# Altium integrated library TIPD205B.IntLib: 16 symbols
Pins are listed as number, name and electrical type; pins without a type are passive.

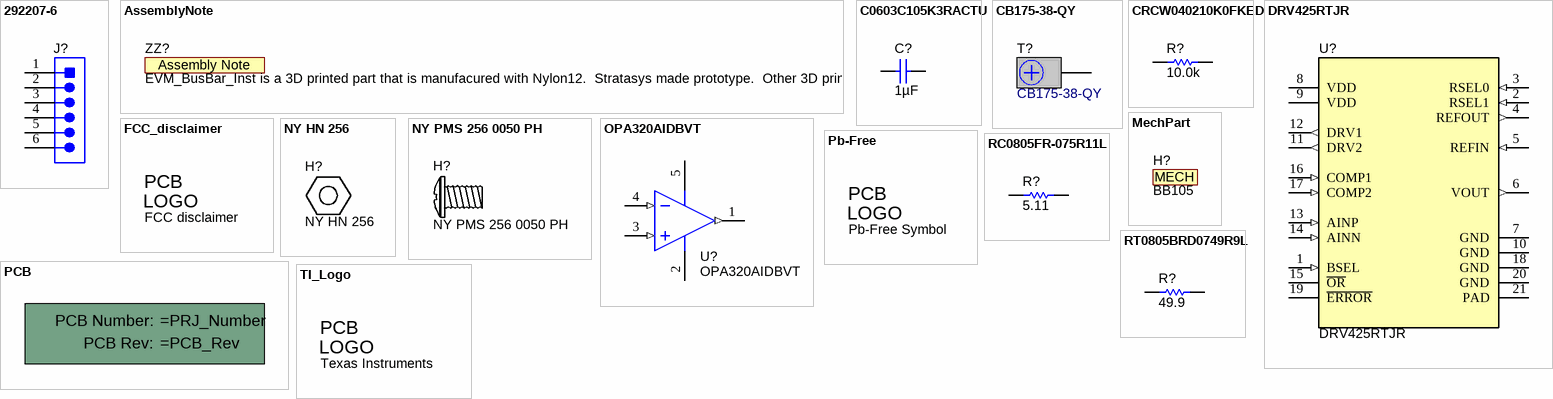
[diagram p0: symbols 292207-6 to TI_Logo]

## 292207-6
designator J?  (value not drawn)
Header(shrouded), 1.5mm, 6x1, Tin, TH; Manufacturer: TE Connectivity; SymbolCreator: a0412235; Pitch_mm: 1.5; Gender: Male; Shrouded: Y; Row_Count: 1; Current_A: 2; Voltage_V: 50
footprint TE_292207-6
pins: 1, 2, 3, 4, 5, 6

## AssemblyNote
designator ZZ?, comment EVM_BusBar_Inst is a 3D printed part that is manufacured with Nylon12.  Stratasys made prototype.  Other 3D print manufacure can be used.  File types provided (SLDPRT, STEP, STL)  (no BOM)
SymbolCreator: codlsc; CompType: AssemblyNote
footprint AssemblyNote

## C0603C105K3RACTU
designator C?  ValueDisplayed: 1µF  (hidden comment: C0603C105K3RACTU)
CAP, CERM, 1 µF, 25 V, +/- 10%, X7R, 0603; Manufacturer: Kemet; Polarized: N; CompType: Capacitor; Value: 1uF; U/M: EA; Cap_F: 0.000001; Tolerance_%: 10; Value1: Unknown; VDC_V: 25; Value2: 25V; TaMin_C: -55; TaMax_C: 125; Cap_Case: 0603; SizeArea_mm2: 1.28; SizeAreaWB_mm2: 4.68; SizeX_mm: 1.6; SizeY_mm: 0.8; SizeZ_mm: 1; AEC Category: Q200
signal-integrity model Cap
simulation model Cap
footprint 0603
footprint 0603M
footprint 0603L
footprint 0603_HV
footprint 0603S
pins: 1, 2

## CB175-38-QY
designator T?
Lug, Rectangular, 3/0-4 AWG, 3/8 Stud, with screw; Manufacturer: Panduit; SymbolCreator: crossc
footprint Panduit_CB175-38-QY
pins: 1

## CRCW040210K0FKED
designator R?  ValueDisplayed: 10.0k  (hidden comment: CRCW040210K0FKED)
RES, 10.0 k, 1%, 0.063 W, 0402; Manufacturer: Vishay-Dale; CompType: Resistor; Value: 10.0k; U/M: EA; Res_ohm: 10000; Value_Code: 10k0; Tolerance_%: 1; Power_W: 0.063; Value2: 0.063W; VDC_V: 50; TempCo: 100 ppm/C; SizeArea_mm2: 0.5; SizeZ_mm: 0.6; EIA_Code: E96; AEC Category: Q200
signal-integrity model Resistor
simulation model Resistor
footprint 0402
footprint 0402M
footprint 0402L
footprint 0402S
pins: 1, 2

## DRV425RTJR
designator U?
Fully Integrated Precision Fluxgate Magnetic Field Sensor and readout, RTJ0020G (WQFN-20); Alternate PartNumber: DRV425RTJT; Manufacturer: Texas Instruments; SymbolCreator: Altium; CompType: IC; U/M: EA; SizeArea_mm2: 16; SizeAreaWB_mm2: 25; SizeX_mm: 4; SizeZ_mm: 0.8
footprint RTJ0020G
footprint RTJ20_no_vias
pins: 1 BSEL (in), 2 RSEL1 (in), 3 RSEL0 (in), 4 REFOUT (out), 5 REFIN (in), 6 VOUT (out), 7 GND (power), 8 VDD (power), 9 VDD (power), 10 GND (power), 11 DRV2 (out), 12 DRV1 (out), 13 AINP (in), 14 AINN (in), 15 ~{OR} (oc), 16 COMP1 (in), 17 COMP2 (in), 18 GND (power), 19 ~{ERROR} (oc), 20 GND (power), 21 PAD (power)

## FCC_disclaimer
designator Logo?, comment FCC disclaimer  (no BOM)
FCC_disclaimer; SymbolCreator: a0412235
footprint FCC_disclaimer
footprint FCC_disclaimer_stacked

## MechPart
designator H?, comment BB105  (mechanical)
Bus bar 0.4" hole, standoffs, nuts, washers; Manufacturer: Storm Power Components; SymbolCreator: codlsc; CompType: Mechanical; U/M: EA

## NY HN 256
designator H?  (mechanical)
Nylon Nut, 2-56, 3/16"; Manufacturer: B&F Fastener Supply; SymbolCreator: a0412235

## NY PMS 256 0050 PH
designator H?  (mechanical)
Screw, Pan Philips, Nylon, 2-56; Manufacturer: B&F Fastener Supply; SymbolCreator: a0412235

## OPA320AIDBVT
designator U?
Precision, 20 MHz, 0.9 pA Ib, RRIO, CMOS Operational Amplifier, 1.8 to 5.5 V, -40 to 125 degC, 5-pin SOT23 (DBV0005A), Green (RoHS & no Sb/Br); Manufacturer: Texas Instruments; Alternate PartNumber: Equivalent; CMRR(Min)(dB): 100; IIB(Max)(pA): 0.9; Iq per channel(Max)(mA): 1.75; Number of Channels: 2; Offset Drift(Typ)(uV/C): 1.5; Slew Rate(Typ)(V/us): 10; Sub Family: High Output Current Amplifier (>=50mA), Low Input Bias Current Amp (<=10pA), Low Noise Amp (<=10nV/rtHz), Low Offset Voltage Amplifier (<=500uV), Low Supply Voltage Amplifier (<=2.7V), Precision Amplifier; Total Supply Voltage(Max)(+5V is 5, +/-5V is 10): 5.5; Total Supply Voltage(Min)(+5V is 5, +/-5V is 10): 1.8; Vio (25C)(Max)(mV): 0.15; Vn at 1kHz(Typ)(nV/rtHz): 8.5
footprint DBV0005A_N (SOT23, 5-Leads, Body 2.9x1.6mm, Pitch 0.95mm, IPC Medium Density)
footprint DBV0005A_L (SOT23, 5-Leads, Body 2.9x1.6mm, Pitch 0.95mm, IPC Low Density)
footprint DBV0005A_M (SOT23, 5-Leads, Body 2.9x1.6mm, Pitch 0.95mm, IPC Low Density)
pins: 1 OUT (out), 2 V- (power), 3 IN+ (in), 4 IN- (in), 5 V+ (power)

## Pb-Free
designator Logo?, comment Pb-Free Symbol  (no BOM)
SymbolCreator: a0412235
footprint Pb-Free_Overlay_Medium
footprint Pb-Free_Overlay_Small

## PCB
designator !PCB?, comment Printed Circuit Board  (value not drawn)  (mechanical)
Manufacturer: Any; SymbolCreator: a0412235; CompType: PCB
1 alternate drawing of the same symbol

## RC0805FR-075R11L
designator R?  ValueDisplayed: 5.11  (hidden comment: RC0805FR-075R11L)
RES, 5.11, 1%, 0.125 W, 0805; Manufacturer: Yageo America; CompType: Resistor; Value: 5.11; U/M: EA; Value_Code: 5R11; Tolerance_%: 1; Power_W: 0.125; Value2: 0.125W; VDC_V: 150; TempCo: 200 ppm/C; SizeArea_mm2: 2.5; SizeX_mm: 2; SizeY_mm: 1.25; SizeZ_mm: 1.45; EIA_Code: E96; AEC Category: Q200
signal-integrity model Resistor
simulation model Resistor
footprint 0805_HV
footprint 0805_HV1
footprint 0805
footprint 0805M
footprint 0805L
pins: 1, 2

## RT0805BRD0749R9L
designator R?  ValueDisplayed: 49.9  (hidden comment: RT0805BRD0749R9L)
RES, 49.9, 0.1%, 0.125 W, 0805; Manufacturer: Yageo America; CompType: Resistor; Value: 49.9; U/M: EA; Value_Code: 49R9; Tolerance_%: 0.1; Power_W: 0.125; Value2: 0.125W; VDC_V: 150; TempCo: 25 ppm/C; SizeArea_mm2: 2.5; SizeX_mm: 2; SizeY_mm: 1.25; SizeZ_mm: 1.45; EIA_Code: E192; AEC Category: Q200
signal-integrity model Resistor
simulation model Resistor
footprint 0805_HV
footprint 0805_HV1
footprint 0805
footprint 0805M
footprint 0805L
pins: 1, 2

## TI_Logo
designator Logo?, comment Texas Instruments  (no BOM)
Texas Instrument Corporate Signature; SymbolCreator: a0412235
footprint TI_Stacked_SolderMask_Medium
footprint TI_Stacked_SolderMask_Medium_Vertical
footprint TI_Stacked_SolderMask_Small
footprint TI_Stacked_SolderMask_Small_Vertical
footprint TI_Stacked_Overlay_Medium
footprint TI_Stacked_Overlay_Medium_Vertical
footprint TI_Stacked_Overlay_Small
footprint TI_Stacked_Overlay_Small_Vertical
footprint TI_Horizontal_SolderMask_Small
footprint TI_Horizontal_Overlay_Medium
footprint TI_Horizontal_Overlay_Small
footprint TI_Symbol_SolderMask_Medium
footprint TI_Symbol_SolderMask_Small
footprint TI_Symbol_Overlay_Medium
footprint TI_Symbol_Overlay_Small
footprint TI_Horizontal_SolderMask_Medium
